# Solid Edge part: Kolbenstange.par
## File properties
Username: bmolnar
Dokumentum tartalom típus: 0
Author: bmolnar
Last saved by: bmolnar
Revision: 80
Sűrűség: 0,000 kg/m^3
Pontosság: 0,990
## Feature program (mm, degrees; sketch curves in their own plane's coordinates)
base feature "unnamed BaseFeature 1"
thread "unnamed Thread 1"
sketch for "unnamed Protrusion 1" plane through (81, 0, 0) normal (1, 0, 0) x-axis (0, 0, 1)
  circle centre (0, 0) radius 40
extrude "unnamed Protrusion 1" add finite 24 along -normal
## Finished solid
Body 1: solid body, 17 faces, 23 edges, 8 vertices.
  Faces by surface: plane 8, cylinder 4, torus 3, cone 2
  Edges by curve: circle 13, line 6, ellipse 2, intersection 2
Bounding box of the edges (mm; curved faces can reach further): 101.000 x 80.000 x 80.000, from (-20, -40, -40) to (81, 40, 40).
Cylindrical faces by radius (mm): R6.75 x1, R8 x1, R10 x1, R40 x1
Conical faces (half-angle, radius in mm at the cone's reference point): 20 deg R7.4 x1, 60 deg R7.475 x1
Toroidal faces (ring radius, tube radius in mm): R7.15 r0.4 x2, R8.2 r1.8 x1
Planar faces by outward normal: +x 1, +y 1, -x 3, -y 1, oblique 2
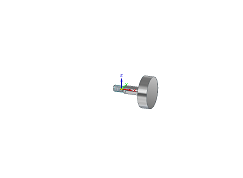
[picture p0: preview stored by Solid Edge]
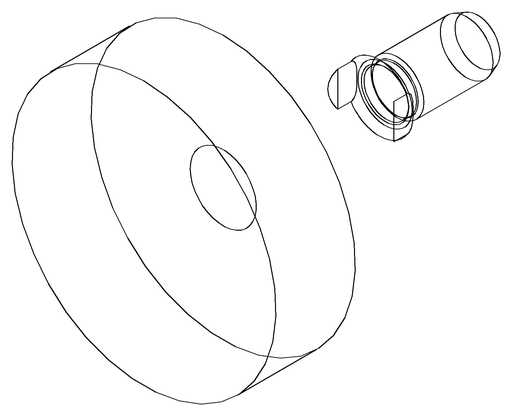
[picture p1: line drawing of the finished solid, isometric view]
